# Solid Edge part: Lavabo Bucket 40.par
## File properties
Title: LAVABO BUCKET 40
Author: DESYS
Template: Iso Part.par
Last saved by: PIM_1
Revision: 48
Application: Solid Edge
Tipo di contenuto documento: 0
Accuracy: 0,990
Document Number: 8803
Revision: 0
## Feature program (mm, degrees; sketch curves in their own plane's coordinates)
lofted protrusion "unnamed LoftedProtrusion 1"
sketch for "ScavoEstrusione_2" plane through (0, 0, 350) normal (0, 0, 1) x-axis (1, 0, 0)
  circle centre (0, 0) radius 167.5
extrude "ScavoEstrusione_2" cut finite 130 along -normal  Treatment1_DraftAngle = 13.5 deg
sketch for "ScavoEstrusione_3" plane through (0, 0, 0) normal (0, 0, -1) x-axis (0, 1, 0)
  circle centre (0, 0) radius 130
extrude "ScavoEstrusione_3" cut finite 205 along -normal
sketch for "ScavoEstrusione_5" plane through (0, 0, 220) normal (0, 0, 1) x-axis (1, 0, 0)
  circle centre (0, 0) radius 22.5
extrude "ScavoEstrusione_5" cut finite 455 along -normal
fillet "Rotondo_1" radius 10
sketch for "ProtrusioneEstrusa_1" #1 plane through (0, 0, 205) normal (0, 0, -1) x-axis (-1, 0, 0)
  circle centre (0, 0) radius 32.5
sketch for "ProtrusioneEstrusa_1" #2 plane through (0, 0, 205) normal (0, 0, -1) x-axis (-1, 0, 0)
  circle centre (0, 0) radius 22.5
extrude "ProtrusioneEstrusa_1" add finite 35 along +normal
sketch for "ScavoEstrusione_8" plane through (0, -185, 175) normal (0, -0.996347, -0.085401) x-axis (0, -0.085401, 0.996347)
  circle centre (130.6417, 0) radius 10
extrude "ScavoEstrusione_8" cut finite 5 along -normal
fillet "Rotondo_2" radius 20
fillet "Rotondo_3" radius 10
fillet "Rotondo_4" radius 5
fillet "Rotondo_5" radius 2
fillet "Rotondo_6" radius 5
fillet "Rotondo_7" radius 2
sketch for "ScavoEstrusione_9" #1 plane through (0, 0, 0) normal (0, 0, -1) x-axis (1, 0, 0)
sketch for "ScavoEstrusione_9" #2 plane through (0, 0, 0) normal (0, 0, -1) x-axis (1, 0, 0)
extrude "ScavoEstrusione_9" cut finite 20 along -normal
fillet "Rotondo_8" radius 2
mirror "unnamed Mirror 1" of "ScavoEstrusione_8", "Rotondo_5" about plane through (31.7919, 0, 31.7919) normal (0, -1, 0)
extrude "unnamed Cutout 1" cut finite 5
fillet "unnamed Round 1"
sketch for "unnamed Cutout 2" #1 plane through (0, 0, 0) normal (0, 0, -1) x-axis (1, 0, 0)
sketch for "unnamed Cutout 2" #2 plane through (0, 0, 0) normal (0, 0, -1) x-axis (1, 0, 0)
  circle centre (-76.0696, -131.0737) radius 10
extrude "unnamed Cutout 2" cut to key point along -normal
fillet "Rotondo_10" radius 2
sketch for "ScavoEstrusione_12" plane through (43.4655, -260, 43.4655) normal (0, -1, 0) x-axis (1, 0, 0)
extrude "ScavoEstrusione_12" cut to key point along -normal  Profile_Plane1_Distance = 260 mm
mirror "unnamed Mirror 2" of "ScavoEstrusione_12" about plane through (27.8179, 0, 27.8179) normal (0, -1, 0)
extrude "unnamed Cutout 3" cut finite 68.8248
fillet "Rotondo_11" radius 2
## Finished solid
Body 1: solid body, 32 faces, 32 edges, 0 vertices.
  Faces by surface: torus 12, plane 9, cylinder 7, blend 2, cone 2
  Edges by curve: circle 28, intersection 4
Bounding box of the edges (mm; curved faces can reach further): 399.070 x 399.070 x 350.000, from (-199.5348, -199.5348, 0) to (199.5348, 199.5348, 350).
Cylindrical faces by radius (mm): R10 x4, R22.5 x1, R32.5 x1, R130 x1
Conical faces (half-angle, radius in mm at the cone's reference point): 4.8991 deg R200 x1, 13.5 deg R167.5 x1
Toroidal faces (ring radius, tube radius in mm): R12 r2 x2, R24.5 r2 x1, R30.5 r2 x1, R32.5 r10 x1, R37.5 r5 x1, R120 r10 x1, R120.523 r20 x1, R135 r5 x1, R165.4102 r5 x1, R171.4417 r5 x1, R194.5531 r5 x1
Planar faces by outward normal: +y 1, +z 2, -y 1, -z 5
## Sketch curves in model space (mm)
circle centre (0, 0, 350) radius 200
circle centre (0, 0, 0) radius 170
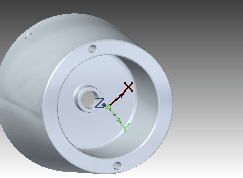
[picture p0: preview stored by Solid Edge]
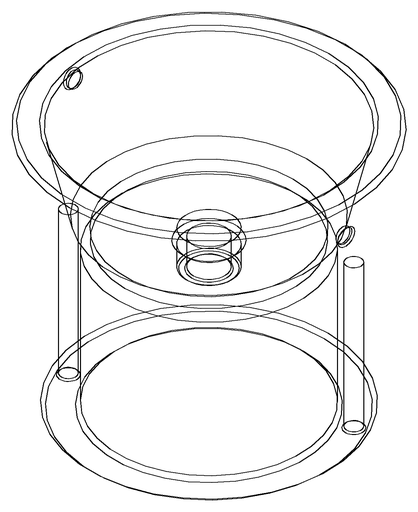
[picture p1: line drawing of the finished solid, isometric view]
